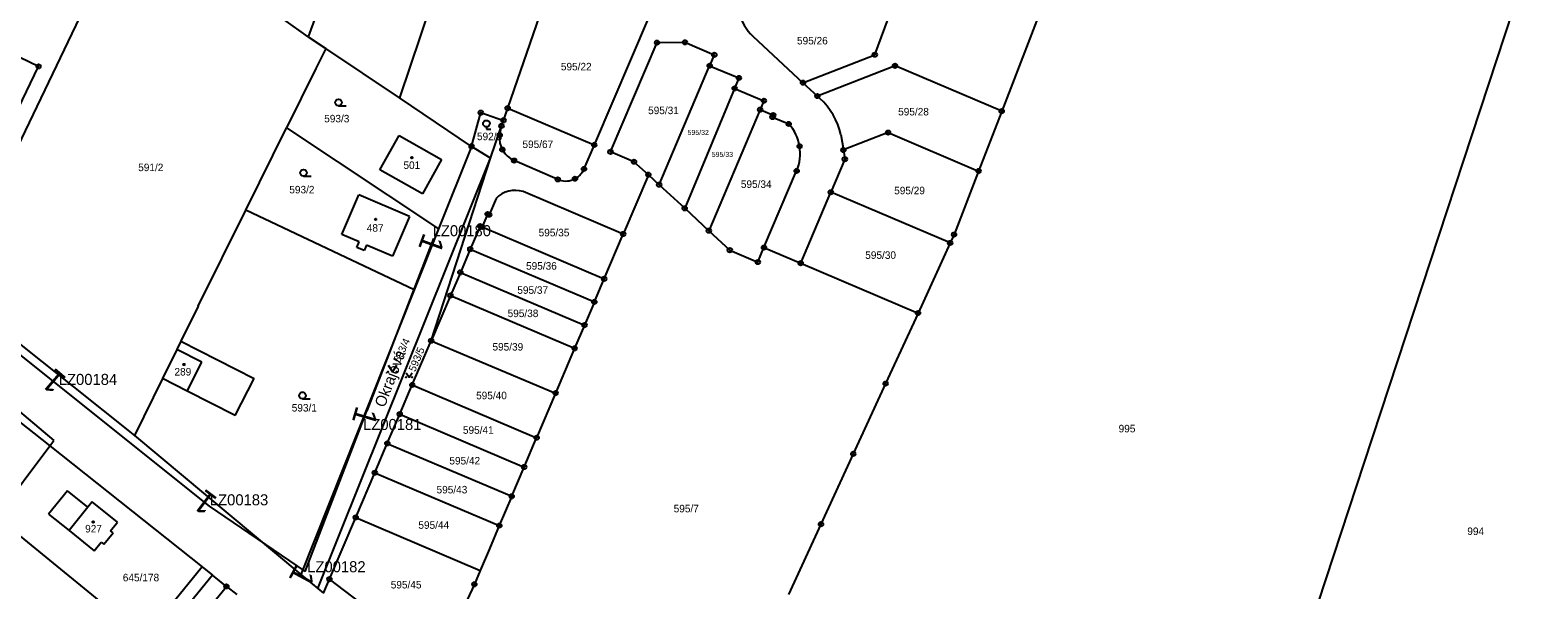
# Model space of a CAD drawing. Extents: x -738131 to -734179, y -1033447 to -1030078.
# Drawn here: x -735741.5 to -735400.6, y -1032530.8 to -1032404.1 of the extents above; entities that cross this region are included whole.
import ezdxf

# ---------------------------------------------------------------- set-up
doc = ezdxf.new("R2010")
doc.units = 0
for name, color, linetype in [('ftf_2010', 7, 'Continuous'), ('ftf_3010', 7, 'Continuous'), ('ftf_3010_ftf_3010_gtda_3015_gtda_3015_1', 7, 'Continuous'), ('ftf_nu', 7, 'Continuous'), ('Vrstva 1', 7, 'Continuous'), ('Vrstva 2', 7, 'Continuous'), ('Vrstva 3', 7, 'Continuous'), ('Vrstva 4', 7, 'Continuous'), ('Vrstva 5', 7, 'Continuous'), ('Vrstva 8', 7, 'Continuous')]:
    doc.layers.add(name, color=color, linetype=linetype)

msp = doc.modelspace()

# ---------------------------------------------------------------- linework, layer by layer
at = {"layer": 'ftf_2010'}
for points in [[(-735777.75, -1032450.49), (-735735.23, -1032484.5)], [(-735650.28, -1032451.26), (-735665.39, -1032490.3)], [(-735735.23, -1032484.5), (-735700.99, -1032511.85)], [(-735679.34, -1032526.68), (-735665.39, -1032490.3)], [(-735700.99, -1032511.85), (-735679.34, -1032526.68)]]:
    msp.add_lwpolyline(points, dxfattribs=at)
at = {"layer": 'Vrstva 1'}
for points in [[(-735622.58, -1032314.16), (-735658, -1032419.49)], [(-735718.91, -1032377.32), (-735749.73, -1032441.59)], [(-735668.22, -1032377.08), (-735678.64, -1032405.65)], [(-735400.56, -1032382.31), (-735439.82, -1032501.93)], [(-735509.1, -1032389.54), (-735521.81, -1032422.48)], [(-735678.64, -1032405.65), (-735695.15, -1032393.79)], [(-735633.52, -1032421.79), (-735624.82, -1032396.59)], [(-735601.55, -1032400.99), (-735613.94, -1032430.11)], [(-735550.49, -1032409.71), (-735547.47, -1032401.6)], [(-735739.59, -1032412.35), (-735752.67, -1032406.11)], [(-735678.64, -1032405.65), (-735674.65, -1032408.31)], [(-735674.65, -1032408.31), (-735676.87, -1032412.8)], [(-735658, -1032419.49), (-735674.65, -1032408.31)], [(-735610.26, -1032431.68), (-735599.74, -1032406.95)], [(-735599.74, -1032406.95), (-735593.43, -1032406.89)], [(-735593.43, -1032406.89), (-735586.79, -1032409.72)], [(-735578.03, -1032405.56), (-735566.74, -1032416.03)], [(-735586.79, -1032409.72), (-735587.85, -1032412.19)], [(-735566.74, -1032416.03), (-735550.49, -1032409.71)], [(-735762.32, -1032459.53), (-735739.59, -1032412.35)], [(-735676.87, -1032412.8), (-735683.52, -1032426.26)], [(-735599.26, -1032439.11), (-735587.85, -1032412.19)], [(-735587.85, -1032412.19), (-735581.22, -1032414.96)], [(-735581.22, -1032414.96), (-735582.2, -1032417.33)], [(-735545.93, -1032412.22), (-735563.48, -1032419.06)], [(-735521.81, -1032422.48), (-735545.93, -1032412.22)], [(-735582.2, -1032417.33), (-735593.49, -1032444.46)], [(-735582.2, -1032417.33), (-735575.57, -1032420.12)], [(-735566.74, -1032416.03), (-735563.48, -1032419.06)], [(-735641.69, -1032430.44), (-735658, -1032419.49)], [(-735634.47, -1032424.55), (-735633.52, -1032421.79)], [(-735633.52, -1032421.79), (-735613.94, -1032430.11)], [(-735576.42, -1032422.13), (-735588.04, -1032449.52)], [(-735575.57, -1032420.12), (-735576.42, -1032422.13)], [(-735576.42, -1032422.13), (-735573.48, -1032423.38)], [(-735563.48, -1032419.06), (-735562.91, -1032419.58)], [(-735641.69, -1032430.44), (-735639.59, -1032422.81), (-735634.47, -1032424.55)], [(-735634.91, -1032425.82), (-735634.47, -1032424.55)], [(-735573.48, -1032423.38), (-735573.64, -1032423.8)], [(-735573.64, -1032423.8), (-735569.96, -1032425.37)], [(-735521.81, -1032422.48), (-735527.03, -1032436.02)], [(-735692.73, -1032444.87), (-735683.52, -1032426.26)], [(-735683.52, -1032426.26), (-735649.14, -1032449.13)], [(-735662.46, -1032435.73), (-735658.09, -1032427.97)], [(-735658.09, -1032427.97), (-735648.46, -1032433.43)], [(-735637.44, -1032433.14), (-735634.91, -1032425.82)], [(-735635.32, -1032427.9), (-735634.91, -1032425.82)], [(-735558.17, -1032427.78), (-735557.6, -1032431.26)], [(-735547.49, -1032427.32), (-735557.6, -1032431.26)], [(-735547.49, -1032427.32), (-735527.03, -1032436.02)], [(-735641.69, -1032430.44), (-735649.14, -1032449.13)], [(-735637.44, -1032433.14), (-735641.69, -1032430.44)], [(-735613.94, -1032430.11), (-735616.26, -1032435.55)], [(-735604.96, -1032433.93), (-735610.26, -1032431.68)], [(-735557.6, -1032431.26), (-735557.27, -1032433.34)], [(-735811.27, -1032433.53), (-735736.15, -1032496.99)], [(-735676.47, -1032530.53), (-735637.44, -1032433.14)], [(-735652.79, -1032441.18), (-735662.46, -1032435.73)], [(-735648.46, -1032433.43), (-735652.79, -1032441.18)], [(-735650.83, -1032474.43), (-735637.44, -1032433.14)], [(-735622.19, -1032437.92), (-735632.05, -1032433.65)], [(-735601.7, -1032436.85), (-735604.96, -1032433.93)], [(-735575.56, -1032453.34), (-735568.17, -1032436)], [(-735557.27, -1032433.34), (-735560.44, -1032440.83)], [(-735601.7, -1032436.85), (-735607.4, -1032450.28)], [(-735601.7, -1032436.85), (-735599.26, -1032439.11)], [(-735599.26, -1032439.11), (-735593.49, -1032444.46)], [(-735527.03, -1032436.02), (-735532.58, -1032450.4)], [(-735671.02, -1032450.39), (-735667.18, -1032441.43)], [(-735655.69, -1032446.35), (-735667.18, -1032441.43)], [(-735636.14, -1032442.24), (-735637.7, -1032445.92)], [(-735607.4, -1032450.28), (-735629.99, -1032440.68)], [(-735567.26, -1032456.87), (-735560.44, -1032440.83)], [(-735533.45, -1032452.3), (-735560.44, -1032440.83)], [(-735703.49, -1032466.63), (-735692.73, -1032444.87)], [(-735654.63, -1032462.91), (-735692.73, -1032444.87)], [(-735638.06, -1032445.77), (-735639.3, -1032448.68)], [(-735637.7, -1032445.92), (-735638.06, -1032445.77)], [(-735593.49, -1032444.46), (-735588.04, -1032449.52)], [(-735655.69, -1032446.35), (-735659.53, -1032455.31)], [(-735649.14, -1032449.13), (-735654.63, -1032462.91)], [(-735639.77, -1032448.48), (-735641.99, -1032453.7)], [(-735639.3, -1032448.68), (-735639.77, -1032448.48)], [(-735639.3, -1032448.68), (-735611.7, -1032460.41)], [(-735588.04, -1032449.52), (-735583.28, -1032453.93)], [(-735667.11, -1032452.06), (-735671.02, -1032450.39)], [(-735667.64, -1032453.3), (-735667.11, -1032452.06)], [(-735665.46, -1032452.77), (-735665.99, -1032454)], [(-735659.53, -1032455.31), (-735665.46, -1032452.77)], [(-735611.7, -1032460.41), (-735607.4, -1032450.28)], [(-735533.45, -1032452.3), (-735540.73, -1032468.16)], [(-735532.58, -1032450.4), (-735533.45, -1032452.3)], [(-735665.99, -1032454), (-735667.64, -1032453.3)], [(-735641.99, -1032453.7), (-735644.22, -1032458.95)], [(-735641.99, -1032453.7), (-735613.92, -1032465.64)], [(-735583.28, -1032453.93), (-735576.95, -1032456.63)], [(-735576.95, -1032456.63), (-735575.56, -1032453.34)], [(-735575.56, -1032453.34), (-735567.26, -1032456.87)], [(-735644.22, -1032458.95), (-735646.45, -1032464.2)], [(-735644.22, -1032458.95), (-735616.15, -1032470.88)], [(-735567.26, -1032456.87), (-735540.73, -1032468.16)], [(-735759.77, -1032462.52), (-735717.94, -1032495.86)], [(-735654.63, -1032462.91), (-735680.31, -1032527.32)], [(-735613.92, -1032465.64), (-735611.7, -1032460.41)], [(-735703.49, -1032466.63), (-735707.41, -1032474.55)], [(-735646.45, -1032464.2), (-735650.83, -1032474.43)], [(-735646.45, -1032464.2), (-735618.38, -1032476.14)], [(-735613.92, -1032465.64), (-735616.15, -1032470.88)], [(-735540.73, -1032468.16), (-735548.06, -1032484.12)], [(-735616.15, -1032470.88), (-735618.38, -1032476.14)], [(-735708.33, -1032476.42), (-735711.56, -1032482.97)], [(-735707.41, -1032474.55), (-735708.33, -1032476.42)], [(-735707.41, -1032474.55), (-735690.88, -1032482.99)], [(-735655.09, -1032484.43), (-735650.83, -1032474.43)], [(-735650.83, -1032474.43), (-735622.68, -1032486.27)], [(-735618.38, -1032476.14), (-735622.68, -1032486.27)], [(-735711.56, -1032482.97), (-735717.94, -1032495.86)], [(-735706, -1032485.81), (-735711.56, -1032482.97)], [(-735695.15, -1032491.35), (-735690.88, -1032482.99)], [(-735695.15, -1032491.35), (-735706, -1032485.81)], [(-735657.92, -1032491.05), (-735655.09, -1032484.43)], [(-735655.09, -1032484.43), (-735626.97, -1032496.38)], [(-735622.68, -1032486.27), (-735626.97, -1032496.38)], [(-735548.06, -1032484.12), (-735555.37, -1032500.03)], [(-735745.74, -1032491.33), (-735737.09, -1032498.24)], [(-735660.74, -1032497.67), (-735657.92, -1032491.05)], [(-735657.92, -1032491.05), (-735629.79, -1032503.01)], [(-735737.09, -1032498.24), (-735736.15, -1032496.99)], [(-735717.94, -1032495.86), (-735680.31, -1032527.32)], [(-735629.79, -1032503.01), (-735626.97, -1032496.38)], [(-735748.99, -1032514.05), (-735737.09, -1032498.24)], [(-735737.09, -1032498.24), (-735702.58, -1032525.63)], [(-735663.56, -1032504.3), (-735660.74, -1032497.67)], [(-735660.74, -1032497.67), (-735632.6, -1032509.64)], [(-735555.37, -1032500.03), (-735562.67, -1032515.95)], [(-735632.6, -1032509.64), (-735629.79, -1032503.01)], [(-735439.82, -1032501.93), (-735483.48, -1032634.84)], [(-735667.88, -1032514.42), (-735663.56, -1032504.3)], [(-735663.56, -1032504.3), (-735635.41, -1032516.27)], [(-735733.07, -1032508.38), (-735737.38, -1032513.66)], [(-735728.46, -1032512.13), (-735733.07, -1032508.38)], [(-735727.47, -1032510.92), (-735728.46, -1032512.13)], [(-735721.78, -1032515.46), (-735727.47, -1032510.92)], [(-735632.6, -1032509.64), (-735635.41, -1032516.27)], [(-735749.18, -1032514.31), (-735715.63, -1032541.65)], [(-735737.38, -1032513.66), (-735732.71, -1032517.38)], [(-735673.83, -1032528.38), (-735667.88, -1032514.42)], [(-735667.88, -1032514.42), (-735639.71, -1032526.39)], [(-735732.71, -1032517.38), (-735727, -1032521.94)], [(-735723.34, -1032517.43), (-735721.78, -1032515.46)], [(-735722.77, -1032517.88), (-735723.34, -1032517.43)], [(-735635.41, -1032516.27), (-735637.64, -1032521.51)], [(-735562.67, -1032515.95), (-735569.98, -1032531.86)], [(-735727, -1032521.94), (-735725.43, -1032520)], [(-735725.43, -1032520), (-735724.86, -1032520.46)], [(-735724.86, -1032520.46), (-735722.77, -1032517.88)], [(-735637.64, -1032521.51), (-735639.71, -1032526.39)], [(-735700.24, -1032527.51), (-735768.99, -1032611.83)], [(-735702.58, -1032525.63), (-735715.63, -1032541.65)], [(-735702.58, -1032525.63), (-735700.24, -1032527.51)], [(-735697.13, -1032530.02), (-735700.24, -1032527.51)], [(-735680.31, -1032527.32), (-735676.47, -1032530.53)], [(-735639.71, -1032526.39), (-735641.05, -1032529.55)], [(-735765.88, -1032614.34), (-735697.13, -1032530.02)], [(-735697.13, -1032530.02), (-735694.79, -1032531.88)], [(-735676.47, -1032530.53), (-735675.2, -1032531.59)], [(-735675.2, -1032531.59), (-735673.83, -1032528.38)], [(-735649.22, -1032547.12), (-735673.83, -1032528.38)], [(-735641.05, -1032529.55), (-735649.22, -1032547.12)]]:
    msp.add_lwpolyline(points, dxfattribs=at)
for centre, radius, start, end in [((-735570.57, -1032397.5), 10.98, 160.2628, 227.2362), ((-735573.81, -1032431.35), 16.04, 12.8599, 47.2001), ((-735577.37, -1032432.08), 10, 336.9326, 42.1843), ((-735629.85, -1032428.59), 5.52, 172.7804, 246.473), ((-735620.4, -1032433.79), 4.5, 246.5735, 336.996), ((-735631.83, -1032446.33), 5.94, 71.9554, 136.5113)]:
    msp.add_arc(centre, radius, start, end, dxfattribs=at)
at = {"layer": 'Vrstva 3'}
for p, q in [((-735671.78, -1032421.25), (-735670.03, -1032421.25)), ((-735638.34, -1032426.05), (-735638.34, -1032426.55)), ((-735638.34, -1032426.55), (-735637.34, -1032426.55)), ((-735679.68, -1032437.19), (-735677.93, -1032437.19)), ((-735679.93, -1032487.54), (-735678.18, -1032487.54))]:
    msp.add_line(p, q, dxfattribs=at)
for points in [[(-735660.58, -1032479.98), (-735659.58, -1032481.48), (-735658.58, -1032479.98)], [(-735656.49, -1032481.7), (-735655.82, -1032482.7), (-735655.15, -1032481.7)]]:
    msp.add_lwpolyline(points, dxfattribs=at)
for centre, radius in [((-735671.78, -1032420.5), 0.75), ((-735638.34, -1032425.3), 0.75), ((-735679.68, -1032436.44), 0.75), ((-735660.58, -1032481.48), 0.1), ((-735658.58, -1032481.48), 0.1), ((-735656.49, -1032482.7), 0.067), ((-735655.15, -1032482.7), 0.067), ((-735679.93, -1032486.79), 0.75)]:
    msp.add_circle(centre, radius, dxfattribs=at)
at = {"layer": 'Vrstva 4'}
for points in [[(-735702.68, -1032479.3), (-735708.33, -1032476.42)], [(-735706, -1032485.81), (-735702.68, -1032479.3)], [(-735728.46, -1032512.13), (-735732.71, -1032517.38)]]:
    msp.add_lwpolyline(points, dxfattribs=at)
at = {"layer": 'Vrstva 5'}
for centre in [(-735655.2, -1032432.99), (-735663.36, -1032446.94), (-735706.71, -1032479.8), (-735727.26, -1032515.47)]:
    msp.add_circle(centre, 0.175, dxfattribs=at)
at = {"layer": 'Vrstva 8'}
for centre, radius in [((-735599.74, -1032406.95), 0.5), ((-735599.74, -1032406.95), 0.0303), ((-735593.43, -1032406.89), 0.5), ((-735593.43, -1032406.89), 0.0303), ((-735739.59, -1032412.35), 0.5), ((-735587.85, -1032412.19), 0.5), ((-735586.79, -1032409.72), 0.5), ((-735586.79, -1032409.72), 0.0303), ((-735550.49, -1032409.71), 0.5), ((-735550.49, -1032409.71), 0.0303), ((-735545.93, -1032412.22), 0.5), ((-735739.59, -1032412.35), 0.0303), ((-735587.85, -1032412.19), 0.0303), ((-735581.22, -1032414.96), 0.5), ((-735581.22, -1032414.96), 0.0303), ((-735566.74, -1032416.03), 0.5), ((-735545.93, -1032412.22), 0.0303), ((-735582.2, -1032417.33), 0.5), ((-735582.2, -1032417.33), 0.0303), ((-735566.74, -1032416.03), 0.0303), ((-735563.48, -1032419.06), 0.5), ((-735639.59, -1032422.81), 0.5), ((-735633.52, -1032421.79), 0.5), ((-735633.52, -1032421.79), 0.0303), ((-735576.42, -1032422.13), 0.5), ((-735576.42, -1032422.13), 0.0303), ((-735575.57, -1032420.12), 0.5), ((-735575.57, -1032420.12), 0.0303), ((-735563.48, -1032419.06), 0.0303), ((-735521.81, -1032422.48), 0.5), ((-735521.81, -1032422.48), 0.5), ((-735639.59, -1032422.81), 0.0303), ((-735634.91, -1032425.82), 0.5), ((-735634.47, -1032424.55), 0.5), ((-735634.47, -1032424.55), 0.0303), ((-735573.64, -1032423.8), 0.5), ((-735573.48, -1032423.38), 0.5), ((-735573.64, -1032423.8), 0.0303), ((-735573.48, -1032423.38), 0.0303), ((-735569.96, -1032425.37), 0.5), ((-735569.96, -1032425.37), 0.0303), ((-735521.81, -1032422.48), 0.0303), ((-735521.81, -1032422.48), 0.0303), ((-735635.32, -1032427.9), 0.5), ((-735635.32, -1032427.9), 0.0303), ((-735634.91, -1032425.82), 0.0303), ((-735547.49, -1032427.32), 0.5), ((-735547.49, -1032427.32), 0.0303), ((-735641.69, -1032430.44), 0.5), ((-735641.69, -1032430.44), 0.0303), ((-735634.73, -1032431.16), 0.5), ((-735634.73, -1032431.16), 0.0303), ((-735613.94, -1032430.11), 0.5), ((-735613.94, -1032430.11), 0.0303), ((-735610.26, -1032431.68), 0.5), ((-735610.26, -1032431.68), 0.0303), ((-735567.51, -1032430.42), 0.5), ((-735567.51, -1032430.42), 0.0303), ((-735557.6, -1032431.26), 0.5), ((-735557.6, -1032431.26), 0.0303), ((-735632.05, -1032433.65), 0.5), ((-735632.05, -1032433.65), 0.0303), ((-735616.26, -1032435.55), 0.5), ((-735616.26, -1032435.55), 0.0303), ((-735604.96, -1032433.93), 0.5), ((-735604.96, -1032433.93), 0.0303), ((-735568.17, -1032436), 0.5), ((-735568.17, -1032436), 0.0303), ((-735557.27, -1032433.34), 0.5), ((-735557.27, -1032433.34), 0.0303), ((-735527.03, -1032436.02), 0.5), ((-735527.03, -1032436.02), 0.5), ((-735527.03, -1032436.02), 0.0303), ((-735527.03, -1032436.02), 0.0303), ((-735622.19, -1032437.92), 0.5), ((-735622.19, -1032437.92), 0.0303), ((-735618.3, -1032437.77), 0.5), ((-735618.3, -1032437.77), 0.0303), ((-735601.7, -1032436.85), 0.5), ((-735601.7, -1032436.85), 0.5), ((-735601.7, -1032436.85), 0.0303), ((-735601.7, -1032436.85), 0.0303), ((-735599.26, -1032439.11), 0.5), ((-735599.26, -1032439.11), 0.0303), ((-735560.44, -1032440.83), 0.5), ((-735560.44, -1032440.83), 0.0303), ((-735638.06, -1032445.77), 0.5), ((-735637.7, -1032445.92), 0.5), ((-735638.06, -1032445.77), 0.0303), ((-735637.7, -1032445.92), 0.0303), ((-735593.49, -1032444.46), 0.5), ((-735593.49, -1032444.46), 0.0303), ((-735639.77, -1032448.48), 0.5), ((-735639.3, -1032448.68), 0.5), ((-735639.77, -1032448.48), 0.0303), ((-735639.3, -1032448.68), 0.0303), ((-735588.04, -1032449.52), 0.5), ((-735588.04, -1032449.52), 0.0303), ((-735607.4, -1032450.28), 0.5), ((-735607.4, -1032450.28), 0.0303), ((-735575.56, -1032453.34), 0.5), ((-735575.56, -1032453.34), 0.5), ((-735533.45, -1032452.3), 0.5), ((-735533.45, -1032452.3), 0.5), ((-735533.45, -1032452.3), 0.0303), ((-735533.45, -1032452.3), 0.0303), ((-735532.58, -1032450.4), 0.5), ((-735532.58, -1032450.4), 0.5), ((-735532.58, -1032450.4), 0.0303), ((-735532.58, -1032450.4), 0.0303), ((-735641.99, -1032453.7), 0.5), ((-735641.99, -1032453.7), 0.0303), ((-735583.28, -1032453.93), 0.5), ((-735583.28, -1032453.93), 0.5), ((-735583.28, -1032453.93), 0.0303), ((-735583.28, -1032453.93), 0.0303), ((-735576.95, -1032456.63), 0.5), ((-735576.95, -1032456.63), 0.5), ((-735575.56, -1032453.34), 0.0303), ((-735575.56, -1032453.34), 0.0303), ((-735567.26, -1032456.87), 0.5), ((-735644.22, -1032458.95), 0.5), ((-735644.22, -1032458.95), 0.0303), ((-735576.95, -1032456.63), 0.0303), ((-735576.95, -1032456.63), 0.0303), ((-735567.26, -1032456.87), 0.0303), ((-735611.7, -1032460.41), 0.5), ((-735611.7, -1032460.41), 0.0303), ((-735646.45, -1032464.2), 0.5), ((-735646.45, -1032464.2), 0.0303), ((-735613.92, -1032465.64), 0.5), ((-735613.92, -1032465.64), 0.0303), ((-735540.73, -1032468.16), 0.5), ((-735540.73, -1032468.16), 0.5), ((-735540.73, -1032468.16), 0.0303), ((-735540.73, -1032468.16), 0.0303), ((-735616.15, -1032470.88), 0.5), ((-735616.15, -1032470.88), 0.0303), ((-735650.83, -1032474.43), 0.5), ((-735650.83, -1032474.43), 0.0303), ((-735618.38, -1032476.14), 0.5), ((-735618.38, -1032476.14), 0.0303), ((-735548.06, -1032484.12), 0.5), ((-735655.09, -1032484.43), 0.5), ((-735655.09, -1032484.43), 0.0303), ((-735622.68, -1032486.27), 0.5), ((-735622.68, -1032486.27), 0.0303), ((-735548.06, -1032484.12), 0.0303), ((-735657.92, -1032491.05), 0.5), ((-735657.92, -1032491.05), 0.0303), ((-735660.74, -1032497.67), 0.5), ((-735626.97, -1032496.38), 0.5), ((-735626.97, -1032496.38), 0.0303), ((-735660.74, -1032497.67), 0.0303), ((-735555.37, -1032500.03), 0.5), ((-735555.37, -1032500.03), 0.0303), ((-735663.56, -1032504.3), 0.5), ((-735629.79, -1032503.01), 0.5), ((-735629.79, -1032503.01), 0.0303), ((-735663.56, -1032504.3), 0.0303), ((-735632.6, -1032509.64), 0.5), ((-735632.6, -1032509.64), 0.0303), ((-735667.88, -1032514.42), 0.5), ((-735667.88, -1032514.42), 0.0303), ((-735635.41, -1032516.27), 0.5), ((-735635.41, -1032516.27), 0.0303), ((-735562.67, -1032515.95), 0.5), ((-735562.67, -1032515.95), 0.0303), ((-735673.83, -1032528.38), 0.5), ((-735697.13, -1032530.02), 0.5), ((-735697.13, -1032530.02), 0.0303), ((-735673.83, -1032528.38), 0.0303), ((-735641.05, -1032529.55), 0.5), ((-735641.05, -1032529.55), 0.5), ((-735641.05, -1032529.55), 0.0303), ((-735641.05, -1032529.55), 0.0303)]:
    msp.add_circle(centre, radius, dxfattribs=at)

# ---------------------------------------------------------------- texts
at = {"layer": 'ftf_3010'}
for rotation, p in [(250.0383, (-735652.5, -1032449.77)), (139.2546, (-735733.04, -1032482.95)), (253.6177, (-735667.7, -1032488.94)), (143.0471, (-735698.9, -1032510.16)), (241.7532, (-735681.33, -1032524.88))]:
    msp.add_text('1', height=5.2, rotation=rotation, dxfattribs=at).set_placement(p)
at = {"layer": 'ftf_3010_ftf_3010_gtda_3015_gtda_3015_1'}
for s, p in [('LZ00180', (-735650.49, -1032450.78)), ('LZ00184', (-735735.03, -1032484.43)), ('LZ00181', (-735666.22, -1032494.63)), ('LZ00183', (-735700.86, -1032511.68)), ('LZ00182', (-735678.85, -1032526.82))]:
    msp.add_text(s, height=2.5, dxfattribs=at).set_placement(p)
at = {"layer": 'ftf_nu'}
msp.add_text('Okrajová', height=2.5, rotation=68.9741, dxfattribs=at).set_placement((-735661.36, -1032489.69))
at = {"layer": 'Vrstva 2'}
for s, height, p in [('595/26', 1.7, (-735568.09, -1032407.37)), ('595/22', 1.7, (-735621.49, -1032413.24)), ('595/31', 1.7, (-735601.76, -1032423.15)), ('595/28', 1.7, (-735545.22, -1032423.44)), ('593/3', 1.7, (-735675.01, -1032425.01)), ('592/3', 1.7, (-735640.46, -1032429.04)), ('595/67', 1.7, (-735630.18, -1032430.82)), ('595/32', 1.14, (-735592.83, -1032427.86)), ('595/33', 1.14, (-735587.37, -1032432.83)), ('591/2', 1.7, (-735717.07, -1032436.05)), ('501', 1.7, (-735657.09, -1032435.55)), ('593/2', 1.7, (-735682.9, -1032441.08)), ('595/34', 1.7, (-735580.79, -1032439.84)), ('595/29', 1.7, (-735546.12, -1032441.28)), ('487', 1.7, (-735665.38, -1032449.75)), ('595/35', 1.7, (-735626.52, -1032450.8)), ('595/30', 1.7, (-735552.66, -1032455.9)), ('595/36', 1.7, (-735629.36, -1032458.34)), ('595/37', 1.7, (-735631.34, -1032463.81)), ('595/38', 1.7, (-735633.53, -1032469.08)), ('595/39', 1.7, (-735636.96, -1032476.65)), ('289', 1.7, (-735708.87, -1032482.3)), ('595/40', 1.7, (-735640.66, -1032487.67)), ('593/1', 1.7, (-735682.35, -1032490.45)), ('595/41', 1.7, (-735643.64, -1032495.49)), ('995', 1.7, (-735495.36, -1032495.16)), ('595/42', 1.7, (-735646.7, -1032502.43)), ('595/43', 1.7, (-735649.6, -1032508.98)), ('595/7', 1.7, (-735595.98, -1032513.26)), ('927', 1.7, (-735729.07, -1032517.81)), ('595/44', 1.7, (-735653.71, -1032516.99)), ('994', 1.7, (-735416.51, -1032518.39)), ('645/178', 1.7, (-735720.55, -1032528.87)), ('595/45', 1.7, (-735659.96, -1032530.49))]:
    msp.add_text(s, height=height, dxfattribs=at).set_placement(p)
for s, rotation, p in [('593/4', 64.7555, (-735657.95, -1032479.55)), ('593/5', 67.2268, (-735654.44, -1032481.59))]:
    msp.add_text(s, height=1.7, rotation=rotation, dxfattribs=at).set_placement(p)

doc.saveas('drawing.dxf')
